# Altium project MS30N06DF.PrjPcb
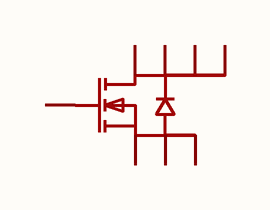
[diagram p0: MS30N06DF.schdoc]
1 sheet, 1 parts. Net scope: global (net labels, ports and power ports of the same name join across sheets).

## Sheet MS30N06DF.schdoc
size 127 x 101 mm

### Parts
U?  ms30n06df  [POWERPAK-1212-8_L3.1-W3.1-P0.65-LS3.3-BL]  (value not drawn)

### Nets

Not connected (* = marked no-connect by the designer): U? 1(S) 2(S) 3(S) 4(G) 5(D) 6(D) 7(D) 8(D)

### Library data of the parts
U? = ms30n06df: 数量:1个N沟道;漏源电压(Vdss):60V;连续漏极电流(Id):30A;导通电阻(RDS(on)):36mΩ@10V;耗散功率(Pd):31W;阈值电压(Vgs(th)):2.5V;; Manufacturer: MSKSEMI(美森科); AddInBom: yes; ModelId: dbd84c1e9d2548b691cb9cd1ec71f8f9; ModelTransform: 129.921,129.921,0,0,0,0,0,0.002,0; Number: 1个N沟道; Drain to Source Voltage: 60V; Current - Continuous Drain(Id): 30A; Pd - Power Dissipation: 31W; Gate Threshold Voltage (Vgs(th)): 2.5V; Gate Charge(Qg): 16.4nC@10V; Reverse Transfer Capacitance (Crss@Vds): 52pF; Output Capacitance(Coss): 1.18nF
